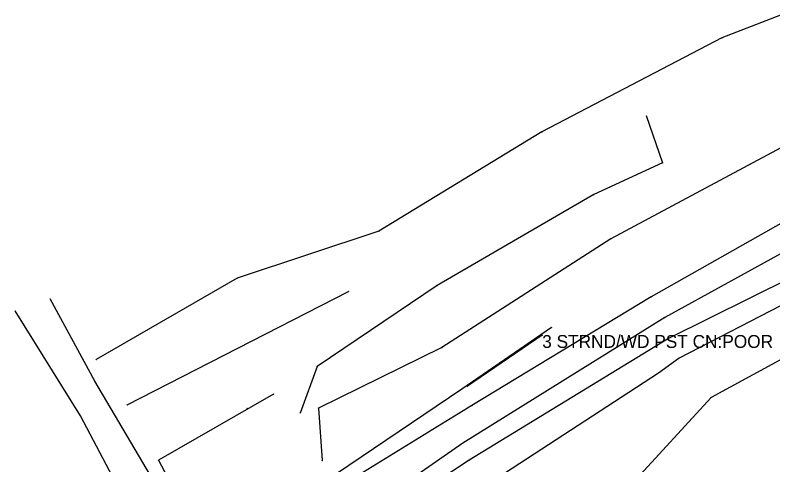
# Model space of a CAD drawing. Extents: x 1419505 to 1434054, y 1956910 to 1968644.
# Drawn here: x 1423011.3 to 1423305.2, y 1959196.4 to 1959370.7 of the extents above; entities that cross this region are included whole.
import ezdxf

# ---------------------------------------------------------------- set-up
doc = ezdxf.new("R2010")
doc.units = 0
for name, color, linetype in [('S_BREAKLINE', 7, 'Continuous'), ('S_DITCHLINE', 7, 'Continuous'), ('S_FENCE', 7, 'Continuous'), ('S_FENCE_ANNOT', 7, 'Continuous'), ('S_GRAVEL_ROAD', 7, 'Continuous'), ('S_GRD_PT_SYM', 7, 'Continuous'), ('S_MSC_PT_SYM', 7, 'Continuous'), ('S_RDW_PT_SYM', 7, 'Continuous')]:
    doc.layers.add(name, color=color, linetype=linetype)

msp = doc.modelspace()

# ---------------------------------------------------------------- linework, layer by layer
at = {"layer": 'S_BREAKLINE'}
for p, q in [((1423308.1598, 1959370.7032), (1423285.4454, 1959361.8876)), ((1423285.4454, 1959361.8876), (1423215.6458, 1959325.4153)), ((1423256.0585, 1959331.8037), (1423262.3579, 1959313.4035)), ((1423325.0419, 1959328.2905), (1423242.3606, 1959283.9216)), ((1423215.6458, 1959325.4153), (1423152.4328, 1959286.9758)), ((1423262.3579, 1959313.4035), (1423235.8021, 1959301.1777)), ((1423336.3566, 1959305.951), (1423258.0326, 1959261.5482)), ((1423235.8021, 1959301.1777), (1423174.9422, 1959265.8384)), ((1423152.4328, 1959286.9758), (1423097.4762, 1959268.7506)), ((1423242.3606, 1959283.9216), (1423176.8333, 1959241.7939)), ((1423353.4707, 1959281.3724), (1423268.8403, 1959237.7196)), ((1423097.4762, 1959268.7506), (1423042.8267, 1959237.2486)), ((1423174.9422, 1959265.8384), (1423128.4292, 1959234.5114)), ((1423360.6302, 1959265.5784), (1423281.2461, 1959222.5136)), ((1423054.8375, 1959219.6444), (1423140.565, 1959263.5833)), ((1423258.0326, 1959261.5482), (1423188.4871, 1959219.3234)), ((1423219.2901, 1959249.5724), (1423184.5148, 1959225.6968)), ((1423176.8333, 1959241.7939), (1423129.0252, 1959218.3944)), ((1423268.8403, 1959237.7196), (1423260.8248, 1959231.9322)), ((1423128.4292, 1959234.5114), (1423121.8848, 1959216.4492)), ((1423260.8248, 1959231.9322), (1423193.4474, 1959188.0554)), ((1423111.5891, 1959223.8027), (1423066.9272, 1959198.1301)), ((1423184.5148, 1959225.6968), (1423116.4284, 1959179.7229)), ((1423281.2461, 1959222.5136), (1423218.287, 1959153.8762)), ((1423188.4871, 1959219.3234), (1423112.7502, 1959172.9554)), ((1423129.0252, 1959218.3944), (1423130.4553, 1959197.999)), ((1423066.9272, 1959198.1301), (1423082.8213, 1959168.1511))]:
    msp.add_line(p, q, dxfattribs=at)
at = {"layer": 'S_DITCHLINE'}
for p, q in [((1423342.414, 1959297.0324), (1423263.3349, 1959253.5036)), ((1423348.4494, 1959286.9208), (1423264.672, 1959245.3701)), ((1423263.3349, 1959253.5036), (1423184.9459, 1959204.7635)), ((1423264.672, 1959245.3701), (1423187.455, 1959198.2291)), ((1423184.9459, 1959204.7635), (1423119.9397, 1959159.6596)), ((1423187.455, 1959198.2291), (1423121.8368, 1959155.1663))]:
    msp.add_line(p, q, dxfattribs=at)
at = {"layer": 'S_FENCE'}
msp.add_line((1423215.7388, 1959246.6932), (1423186.749, 1959226.8489), dxfattribs=at)
at = {"layer": 'S_GRAVEL_ROAD'}
for p, q in [((1423042.2936, 1959228.774), (1423024.9205, 1959260.7101)), ((1423036.7293, 1959215.3232), (1423011.3987, 1959256.0578)), ((1423070.1264, 1959181.533), (1423042.2936, 1959228.774)), ((1423058.3767, 1959174.1935), (1423036.7293, 1959215.3232))]:
    msp.add_line(p, q, dxfattribs=at)
at = {"layer": 'S_GRD_PT_SYM'}
for points in [[(1423285.4454, 1959361.8876), (1423285.4454, 1959361.9376), (1423285.4454, 1959361.8876), (1423285.3954, 1959361.8876), (1423285.4454, 1959361.8876), (1423285.4454, 1959361.8376), (1423285.4454, 1959361.8876), (1423285.4954, 1959361.8876)], [(1423256.0585, 1959331.8037), (1423256.0585, 1959331.8537), (1423256.0585, 1959331.8037), (1423256.0085, 1959331.8037), (1423256.0585, 1959331.8037), (1423256.0585, 1959331.7537), (1423256.0585, 1959331.8037), (1423256.1085, 1959331.8037)], [(1423215.6458, 1959325.4153), (1423215.6458, 1959325.4653), (1423215.6458, 1959325.4153), (1423215.5958, 1959325.4153), (1423215.6458, 1959325.4153), (1423215.6458, 1959325.3653), (1423215.6458, 1959325.4153), (1423215.6958, 1959325.4153)], [(1423262.3579, 1959313.4035), (1423262.3579, 1959313.4535), (1423262.3579, 1959313.4035), (1423262.3079, 1959313.4035), (1423262.3579, 1959313.4035), (1423262.3579, 1959313.3535), (1423262.3579, 1959313.4035), (1423262.4079, 1959313.4035)], [(1423235.8021, 1959301.1777), (1423235.8021, 1959301.2277), (1423235.8021, 1959301.1777), (1423235.7521, 1959301.1777), (1423235.8021, 1959301.1777), (1423235.8021, 1959301.1277), (1423235.8021, 1959301.1777), (1423235.8521, 1959301.1777)], [(1423152.4328, 1959286.9758), (1423152.4328, 1959287.0258), (1423152.4328, 1959286.9758), (1423152.3828, 1959286.9758), (1423152.4328, 1959286.9758), (1423152.4328, 1959286.9258), (1423152.4328, 1959286.9758), (1423152.4828, 1959286.9758)], [(1423242.3606, 1959283.9216), (1423242.3606, 1959283.9716), (1423242.3606, 1959283.9216), (1423242.3106, 1959283.9216), (1423242.3606, 1959283.9216), (1423242.3606, 1959283.8716), (1423242.3606, 1959283.9216), (1423242.4106, 1959283.9216)], [(1423097.4762, 1959268.7506), (1423097.4762, 1959268.8006), (1423097.4762, 1959268.7506), (1423097.4262, 1959268.7506), (1423097.4762, 1959268.7506), (1423097.4762, 1959268.7006), (1423097.4762, 1959268.7506), (1423097.5262, 1959268.7506)], [(1423174.9422, 1959265.8384), (1423174.9422, 1959265.8884), (1423174.9422, 1959265.8384), (1423174.8922, 1959265.8384), (1423174.9422, 1959265.8384), (1423174.9422, 1959265.7884), (1423174.9422, 1959265.8384), (1423174.9922, 1959265.8384)], [(1423140.565, 1959263.5833), (1423140.565, 1959263.6333), (1423140.565, 1959263.5833), (1423140.515, 1959263.5833), (1423140.565, 1959263.5833), (1423140.565, 1959263.5333), (1423140.565, 1959263.5833), (1423140.615, 1959263.5833)], [(1423258.0326, 1959261.5482), (1423258.0326, 1959261.5982), (1423258.0326, 1959261.5482), (1423257.9826, 1959261.5482), (1423258.0326, 1959261.5482), (1423258.0326, 1959261.4982), (1423258.0326, 1959261.5482), (1423258.0826, 1959261.5482)], [(1423263.3349, 1959253.5036), (1423263.3349, 1959253.5536), (1423263.3349, 1959253.5036), (1423263.2849, 1959253.5036), (1423263.3349, 1959253.5036), (1423263.3349, 1959253.4536), (1423263.3349, 1959253.5036), (1423263.3849, 1959253.5036)], [(1423219.2901, 1959249.5724), (1423219.2901, 1959249.6224), (1423219.2901, 1959249.5724), (1423219.2401, 1959249.5724), (1423219.2901, 1959249.5724), (1423219.2901, 1959249.5224), (1423219.2901, 1959249.5724), (1423219.3401, 1959249.5724)], [(1423264.672, 1959245.3701), (1423264.672, 1959245.4201), (1423264.672, 1959245.3701), (1423264.622, 1959245.3701), (1423264.672, 1959245.3701), (1423264.672, 1959245.3201), (1423264.672, 1959245.3701), (1423264.722, 1959245.3701)], [(1423176.8333, 1959241.7939), (1423176.8333, 1959241.8439), (1423176.8333, 1959241.7939), (1423176.7833, 1959241.7939), (1423176.8333, 1959241.7939), (1423176.8333, 1959241.7439), (1423176.8333, 1959241.7939), (1423176.8833, 1959241.7939)], [(1423042.8267, 1959237.2486), (1423042.8267, 1959237.2986), (1423042.8267, 1959237.2486), (1423042.7767, 1959237.2486), (1423042.8267, 1959237.2486), (1423042.8267, 1959237.1986), (1423042.8267, 1959237.2486), (1423042.8767, 1959237.2486)], [(1423268.8403, 1959237.7196), (1423268.8403, 1959237.7696), (1423268.8403, 1959237.7196), (1423268.7903, 1959237.7196), (1423268.8403, 1959237.7196), (1423268.8403, 1959237.6696), (1423268.8403, 1959237.7196), (1423268.8903, 1959237.7196)], [(1423128.4292, 1959234.5114), (1423128.4292, 1959234.5614), (1423128.4292, 1959234.5114), (1423128.3792, 1959234.5114), (1423128.4292, 1959234.5114), (1423128.4292, 1959234.4614), (1423128.4292, 1959234.5114), (1423128.4792, 1959234.5114)], [(1423260.8248, 1959231.9322), (1423260.8248, 1959231.9822), (1423260.8248, 1959231.9322), (1423260.7748, 1959231.9322), (1423260.8248, 1959231.9322), (1423260.8248, 1959231.8822), (1423260.8248, 1959231.9322), (1423260.8748, 1959231.9322)], [(1423111.5891, 1959223.8027), (1423111.5891, 1959223.8527), (1423111.5891, 1959223.8027), (1423111.5391, 1959223.8027), (1423111.5891, 1959223.8027), (1423111.5891, 1959223.7527), (1423111.5891, 1959223.8027), (1423111.6391, 1959223.8027)], [(1423184.5148, 1959225.6968), (1423184.5148, 1959225.7468), (1423184.5148, 1959225.6968), (1423184.4648, 1959225.6968), (1423184.5148, 1959225.6968), (1423184.5148, 1959225.6468), (1423184.5148, 1959225.6968), (1423184.5648, 1959225.6968)], [(1423281.2461, 1959222.5136), (1423281.2461, 1959222.5636), (1423281.2461, 1959222.5136), (1423281.1961, 1959222.5136), (1423281.2461, 1959222.5136), (1423281.2461, 1959222.4636), (1423281.2461, 1959222.5136), (1423281.2961, 1959222.5136)], [(1423054.8375, 1959219.6444), (1423054.8375, 1959219.6944), (1423054.8375, 1959219.6444), (1423054.7875, 1959219.6444), (1423054.8375, 1959219.6444), (1423054.8375, 1959219.5944), (1423054.8375, 1959219.6444), (1423054.8875, 1959219.6444)], [(1423101.3025, 1959218.2694), (1423101.3025, 1959218.3194), (1423101.3025, 1959218.2694), (1423101.2525, 1959218.2694), (1423101.3025, 1959218.2694), (1423101.3025, 1959218.2194), (1423101.3025, 1959218.2694), (1423101.3525, 1959218.2694)], [(1423129.0252, 1959218.3944), (1423129.0252, 1959218.4444), (1423129.0252, 1959218.3944), (1423128.9752, 1959218.3944), (1423129.0252, 1959218.3944), (1423129.0252, 1959218.3444), (1423129.0252, 1959218.3944), (1423129.0752, 1959218.3944)], [(1423188.4871, 1959219.3234), (1423188.4871, 1959219.3734), (1423188.4871, 1959219.3234), (1423188.4371, 1959219.3234), (1423188.4871, 1959219.3234), (1423188.4871, 1959219.2734), (1423188.4871, 1959219.3234), (1423188.5371, 1959219.3234)], [(1423121.8848, 1959216.4492), (1423121.8848, 1959216.4992), (1423121.8848, 1959216.4492), (1423121.8348, 1959216.4492), (1423121.8848, 1959216.4492), (1423121.8848, 1959216.3992), (1423121.8848, 1959216.4492), (1423121.9348, 1959216.4492)], [(1423184.9459, 1959204.7635), (1423184.9459, 1959204.8135), (1423184.9459, 1959204.7635), (1423184.8959, 1959204.7635), (1423184.9459, 1959204.7635), (1423184.9459, 1959204.7135), (1423184.9459, 1959204.7635), (1423184.9959, 1959204.7635)], [(1423066.9272, 1959198.1301), (1423066.9272, 1959198.1801), (1423066.9272, 1959198.1301), (1423066.8772, 1959198.1301), (1423066.9272, 1959198.1301), (1423066.9272, 1959198.0801), (1423066.9272, 1959198.1301), (1423066.9772, 1959198.1301)], [(1423130.4553, 1959197.999), (1423130.4553, 1959198.049), (1423130.4553, 1959197.999), (1423130.4053, 1959197.999), (1423130.4553, 1959197.999), (1423130.4553, 1959197.949), (1423130.4553, 1959197.999), (1423130.5053, 1959197.999)], [(1423187.455, 1959198.2291), (1423187.455, 1959198.2791), (1423187.455, 1959198.2291), (1423187.405, 1959198.2291), (1423187.455, 1959198.2291), (1423187.455, 1959198.1791), (1423187.455, 1959198.2291), (1423187.505, 1959198.2291)]]:
    msp.add_lwpolyline(points, dxfattribs=at)
at = {"layer": 'S_MSC_PT_SYM'}
for points in [[(1423215.7388, 1959246.6932), (1423215.7388, 1959246.7432), (1423215.7388, 1959246.6932), (1423215.6888, 1959246.6932), (1423215.7388, 1959246.6932), (1423215.7388, 1959246.6432), (1423215.7388, 1959246.6932), (1423215.7888, 1959246.6932)], [(1423186.749, 1959226.8489), (1423186.749, 1959226.8989), (1423186.749, 1959226.8489), (1423186.699, 1959226.8489), (1423186.749, 1959226.8489), (1423186.749, 1959226.7989), (1423186.749, 1959226.8489), (1423186.799, 1959226.8489)]]:
    msp.add_lwpolyline(points, dxfattribs=at)
at = {"layer": 'S_RDW_PT_SYM'}
for points in [[(1423024.9205, 1959260.7101), (1423024.9205, 1959260.7601), (1423024.9205, 1959260.7101), (1423024.8705, 1959260.7101), (1423024.9205, 1959260.7101), (1423024.9205, 1959260.6601), (1423024.9205, 1959260.7101), (1423024.9705, 1959260.7101)], [(1423011.3987, 1959256.0578), (1423011.3987, 1959256.1078), (1423011.3987, 1959256.0578), (1423011.3487, 1959256.0578), (1423011.3987, 1959256.0578), (1423011.3987, 1959256.0078), (1423011.3987, 1959256.0578), (1423011.4487, 1959256.0578)], [(1423042.2936, 1959228.774), (1423042.2936, 1959228.824), (1423042.2936, 1959228.774), (1423042.2436, 1959228.774), (1423042.2936, 1959228.774), (1423042.2936, 1959228.724), (1423042.2936, 1959228.774), (1423042.3436, 1959228.774)], [(1423036.7293, 1959215.3232), (1423036.7293, 1959215.3732), (1423036.7293, 1959215.3232), (1423036.6793, 1959215.3232), (1423036.7293, 1959215.3232), (1423036.7293, 1959215.2732), (1423036.7293, 1959215.3232), (1423036.7793, 1959215.3232)]]:
    msp.add_lwpolyline(points, dxfattribs=at)

# ---------------------------------------------------------------- texts
at = {"layer": 'S_FENCE_ANNOT'}
msp.add_text('3 STRND/WD PST CN:POOR', height=5, dxfattribs=at).set_placement((1423215.7388, 1959241.6932))

doc.saveas('drawing.dxf')
